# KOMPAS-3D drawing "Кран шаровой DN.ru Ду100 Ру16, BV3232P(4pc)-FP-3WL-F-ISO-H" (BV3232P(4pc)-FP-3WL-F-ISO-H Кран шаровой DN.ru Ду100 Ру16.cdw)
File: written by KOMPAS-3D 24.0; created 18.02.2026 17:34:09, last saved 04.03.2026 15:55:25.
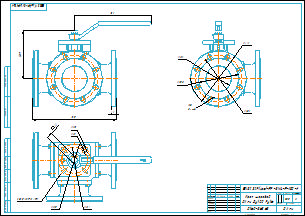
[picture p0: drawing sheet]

Document properties: Автор: R2D2; Форматы листов документа: A2; Полное имя файла: BV3232P(4pc)-FP-3WL-F-ISO-H Кран шаровой DN.ru Ду100 Ру16.m3d; Масса: 58.5; Наименование: Кран шаровой DN.ru Ду100 Ру16; Количество листов документа: 1; Примечание: D160-36363

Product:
- Part/product: Кран шаровой DN.ru Ду100 Ру16  | designation BV3232P(4pc)-FP-3WL-F-ISO-H
    Масса: 58.5
    Раздел спецификации: Прочие изделия
    Примечание: D160-36363

Views: Проекционный вид 2
Referenced files in E:\Работа\Зайцев\BV3232P(4pc)-FP-3WL-F-ISO-H Кран шаровой DN.ru Ду15-100 Ру16\DN100\: BV3232P(4pc)-FP-3WL-F-ISO-H Кран шаровой DN.ru Ду100 Ру16.m3d
Referenced files in E:\Работа\Зайцев\Для компаса\: чертеж DN.ru А3.cdt
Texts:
  BV3232P(4pc)-FP-3WL-F-ISO-H
  чертеж DN.ru А3.cdt
  Кран шаровой
  DN.ru Ду100 Ру16
  Кран шаровой DN.ru Ду100 Ру16
  BV3232P(4pc)-FP-3WL-F-ISO-H Кран шаровой DN.ru Ду100 Ру16
Dimensions and other numbers on the sheet: 0; 3; 4; 220; 180; 158; 18; 8 отв.; 100; 1:2; 1; 2; 58,5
